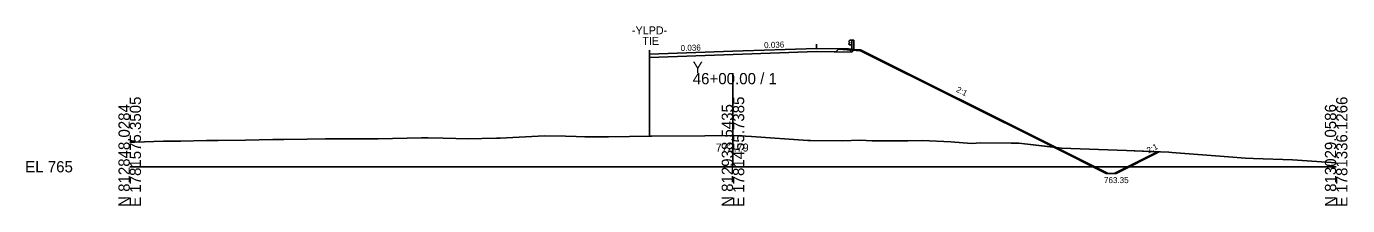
# Model space of a CAD drawing. Extents: x -12583 to 5303, y -44 to 25667.
# Drawn here: x 2974.3 to 3302.8, y 6490.3 to 6535 of the extents above; entities that cross this region are included whole.
import ezdxf

# ---------------------------------------------------------------- set-up
doc = ezdxf.new("R2010")
doc.units = 0
for name, color, linetype in [('Exist Cross Section Cell', 7, 'Continuous'), ('Exist XS Center Line Elevation Label', 7, 'Continuous'), ('Exist XS Ground Line', 7, 'Continuous'), ('Prop XS Ditch Standard Text', 7, 'Continuous'), ('Prop XS Dump Level', 7, 'Continuous'), ('Prop XS Earthwork Shape', 7, 'Continuous'), ('Prop XS EOT Tick Mark', 7, 'Continuous'), ('Prop XS Finish Grade', 7, 'Continuous'), ('Prop XS Finish Grade Earthwork', 7, 'Continuous'), ('Prop XS Finish Grade Paved Shoulder', 7, 'Continuous'), ('Prop XS Finish Grade Pavement', 7, 'Continuous'), ('Prop XS Guardrail', 7, 'Continuous'), ('Prop XS Label Text', 7, 'Continuous'), ('Prop XS Pvmt Edge Slope', 7, 'Continuous'), ('Prop XS SE Text', 7, 'Continuous'), ('Prop XS Side Slope Text', 7, 'Continuous'), ('Prop XS Subgrade Earthwork', 7, 'Continuous')]:
    doc.layers.add(name, color=color, linetype=linetype)

msp = doc.modelspace()

# ---------------------------------------------------------------- linework, layer by layer
at = {"layer": 'Exist Cross Section Cell'}
for p, q in [((3150, 6500), (3150, 6523.36)), ((3000, 6500), (3150, 6500)), ((3150, 6500), (3300, 6500))]:
    msp.add_line(p, q, dxfattribs=at)
at = {"layer": 'Exist XS Ground Line'}
for p, q in [((3000, 6506.14), (3001.26, 6506.15)), ((3001.26, 6506.15), (3008.4, 6506.34)), ((3008.4, 6506.34), (3012.73, 6506.39)), ((3012.73, 6506.39), (3019.11, 6506.52)), ((3019.11, 6506.52), (3021.99, 6506.56)), ((3021.99, 6506.56), (3028.81, 6506.66)), ((3028.81, 6506.66), (3035.61, 6506.79)), ((3035.61, 6506.79), (3036.7, 6506.82)), ((3036.7, 6506.82), (3038.28, 6506.8)), ((3038.28, 6506.8), (3044.1, 6506.86)), ((3044.1, 6506.86), (3048.64, 6506.93)), ((3048.64, 6506.93), (3050.76, 6506.94)), ((3050.76, 6506.94), (3061.75, 6506.98)), ((3061.75, 6506.98), (3072.56, 6507.21)), ((3072.56, 6507.21), (3073.61, 6507.18)), ((3073.61, 6507.18), (3074.17, 6507.18)), ((3074.17, 6507.18), (3077.96, 6507.09)), ((3077.96, 6507.09), (3084.21, 6506.99)), ((3084.21, 6506.99), (3087.58, 6507.03)), ((3087.58, 6507.03), (3091.21, 6507.14)), ((3091.21, 6507.14), (3092.08, 6507.14)), ((3092.08, 6507.14), (3103.13, 6507.67)), ((3103.13, 6507.67), (3108.38, 6507.62)), ((3108.38, 6507.62), (3110.99, 6507.55)), ((3110.99, 6507.55), (3113.19, 6507.48)), ((3113.19, 6507.48), (3119.08, 6507.45)), ((3119.08, 6507.45), (3129.48, 6507.65)), ((3129.48, 6507.65), (3129.81, 6507.65)), ((3129.81, 6507.65), (3143, 6507.71)), ((3143, 6507.71), (3150.19, 6507.79)), ((3150.19, 6507.79), (3154.59, 6507.53)), ((3154.59, 6507.53), (3168.6, 6506.54)), ((3168.6, 6506.54), (3169.29, 6506.52)), ((3169.29, 6506.52), (3177.27, 6506.44)), ((3177.27, 6506.44), (3181.6, 6506.61)), ((3181.6, 6506.61), (3184.62, 6506.46)), ((3184.62, 6506.46), (3193.48, 6506.48)), ((3193.48, 6506.48), (3197.15, 6506.52)), ((3197.15, 6506.52), (3204.15, 6506.19)), ((3204.15, 6506.19), (3209.29, 6505.76)), ((3209.29, 6505.76), (3211.61, 6506)), ((3211.61, 6506), (3219.2, 6505.9)), ((3219.2, 6505.9), (3221.09, 6505.88)), ((3221.09, 6505.88), (3231.68, 6504.63)), ((3231.68, 6504.63), (3247.9, 6504.02)), ((3247.9, 6504.02), (3258.35, 6503.62)), ((3258.35, 6503.62), (3259.15, 6503.58)), ((3259.15, 6503.58), (3273.21, 6502.48)), ((3273.21, 6502.48), (3277.42, 6502.1)), ((3277.42, 6502.1), (3279.41, 6502.04)), ((3279.41, 6502.04), (3289.17, 6501.73)), ((3289.17, 6501.73), (3300, 6501))]:
    msp.add_line(p, q, dxfattribs=at)
at = {"layer": 'Prop XS Dump Level'}
for p, q in [((3129.25, 6528.03), (3150, 6528.77)), ((3150, 6528.77), (3170.75, 6529.51))]:
    msp.add_line(p, q, dxfattribs=at)
at = {"layer": 'Prop XS Earthwork Shape'}
for points in [[(3129.25, 6507.64), (3129.48, 6507.65), (3129.81, 6507.65), (3143, 6507.71), (3150.19, 6507.79), (3154.59, 6507.53), (3168.6, 6506.54), (3169.29, 6506.52), (3177.27, 6506.44), (3181.6, 6506.61), (3184.62, 6506.46), (3193.48, 6506.48), (3197.15, 6506.52), (3204.15, 6506.19), (3209.29, 6505.76), (3211.61, 6506), (3219.2, 6505.9), (3221.09, 6505.88), (3229.78, 6504.86), (3181.75, 6528.87), (3176.25, 6529.31), (3175.56, 6528.62), (3170.76, 6528.72), (3150.03, 6527.98), (3129.25, 6527.24)], [(3244.79, 6498.35), (3255.55, 6503.73), (3247.9, 6504.02), (3231.68, 6504.63), (3229.78, 6504.86), (3242.79, 6498.35)]]:
    msp.add_lwpolyline(points, close=True, dxfattribs=at)
at = {"layer": 'Prop XS EOT Tick Mark'}
for p, q in [((3129.25, 6528.03), (3129.25, 6529.03)), ((3170.75, 6529.51), (3170.75, 6530.51))]:
    msp.add_line(p, q, dxfattribs=at)
at = {"layer": 'Prop XS Finish Grade'}
for p, q in [((3129.25, 6528.03), (3129.25, 6527.24)), ((3178.75, 6529.35), (3180.25, 6529.23))]:
    msp.add_line(p, q, dxfattribs=at)
at = {"layer": 'Prop XS Finish Grade Earthwork'}
for p, q in [((3180.25, 6529.23), (3181.75, 6529.11)), ((3181.75, 6529.11), (3230.41, 6504.78)), ((3129.25, 6507.64), (3129.25, 6527.24)), ((3230.41, 6504.78), (3243.27, 6498.35)), ((3245.27, 6498.35), (3256, 6503.71)), ((3243.27, 6498.35), (3245.27, 6498.35))]:
    msp.add_line(p, q, dxfattribs=at)
at = {"layer": 'Prop XS Finish Grade Paved Shoulder'}
msp.add_line((3170.75, 6529.51), (3178.75, 6529.35), dxfattribs=at)
at = {"layer": 'Prop XS Finish Grade Pavement'}
for p, q in [((3129.25, 6528.03), (3150, 6528.77)), ((3150, 6528.77), (3170.75, 6529.51))]:
    msp.add_line(p, q, dxfattribs=at)
at = {"layer": 'Prop XS Guardrail'}
for p, q in [((3178.78, 6531.31), (3178.75, 6531.25)), ((3178.75, 6531.25), (3178.78, 6531.19)), ((3179.07, 6531.51), (3178.78, 6531.31)), ((3179.57, 6531.51), (3179.07, 6531.51)), ((3180.07, 6531.51), (3179.57, 6531.51)), ((3179.57, 6531.51), (3179.57, 6529.01)), ((3180.07, 6529.01), (3180.07, 6531.51)), ((3178.78, 6530.69), (3178.75, 6530.63)), ((3178.75, 6530.63), (3178.78, 6530.57)), ((3178.78, 6531.19), (3179.07, 6530.99)), ((3179.07, 6530.89), (3178.78, 6530.69)), ((3178.78, 6530.57), (3179.07, 6530.37)), ((3179.07, 6530.99), (3179.07, 6530.89)), ((3179.07, 6530.37), (3179.57, 6530.37))]:
    msp.add_line(p, q, dxfattribs=at)
at = {"layer": 'Prop XS Pvmt Edge Slope'}
msp.add_line((3178.75, 6529.35), (3179.56, 6528.54), dxfattribs=at)
at = {"layer": 'Prop XS Subgrade Earthwork'}
for p, q in [((3129.25, 6527.24), (3150.03, 6527.98)), ((3150.03, 6527.98), (3170.76, 6528.72)), ((3170.76, 6528.72), (3179.56, 6528.54)), ((3179.56, 6528.54), (3180.25, 6529.23))]:
    msp.add_line(p, q, dxfattribs=at)

# ---------------------------------------------------------------- texts
at = {"layer": 'Exist Cross Section Cell'}
for s, p in [('Y', (3140, 6523.36)), ('46+00.00 / 1', (3140, 6520.56)), ('EL 765', (2974, 6498.6))]:
    msp.add_text(s, height=2.8, dxfattribs=at).set_placement(p)
for s, p in [('N 812848.0284', (3000, 6490)), ('E 1781575.3505', (3002.8, 6490)), ('N 812938.5435', (3150, 6490)), ('E 1781455.7385', (3152.8, 6490)), ('N 813029.0586', (3300, 6490)), ('E 1781336.1266', (3302.8, 6490))]:
    msp.add_text(s, height=2.8, rotation=90, dxfattribs=at).set_placement(p)
at = {"layer": 'Exist XS Center Line Elevation Label'}
msp.add_text('772.79', height=2, dxfattribs=at).set_placement((3145.73, 6503.79))
at = {"layer": 'Prop XS Ditch Standard Text'}
msp.add_text('763.35', height=1.5, dxfattribs=at).set_placement((3242.26, 6495.92))
at = {"layer": 'Prop XS Dump Level'}
msp.add_text('Case2', height=0.04, dxfattribs=at).set_placement((3178.75, 6529.07))
at = {"layer": 'Prop XS Label Text'}
for s, p in [('-YLPD-', (3124.89, 6532.99)), ('TIE', (3127.47, 6530.37))]:
    msp.add_text(s, height=2, dxfattribs=at).set_placement(p)
at = {"layer": 'Prop XS SE Text'}
for rotation, p in [(2.0442, (3157.77, 6529.55)), (2.0437, (3137.02, 6528.81))]:
    msp.add_text('0.036', height=1.5, rotation=rotation, dxfattribs=at).set_placement(p)
at = {"layer": 'Prop XS Side Slope Text'}
for rotation, p in [(333.4349, (3205.35, 6518.75)), (26.5651, (3253.34, 6503.28))]:
    msp.add_text('2:1', height=1.5, rotation=rotation, dxfattribs=at).set_placement(p)

doc.saveas('drawing.dxf')
